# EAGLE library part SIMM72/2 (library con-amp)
AMP connector
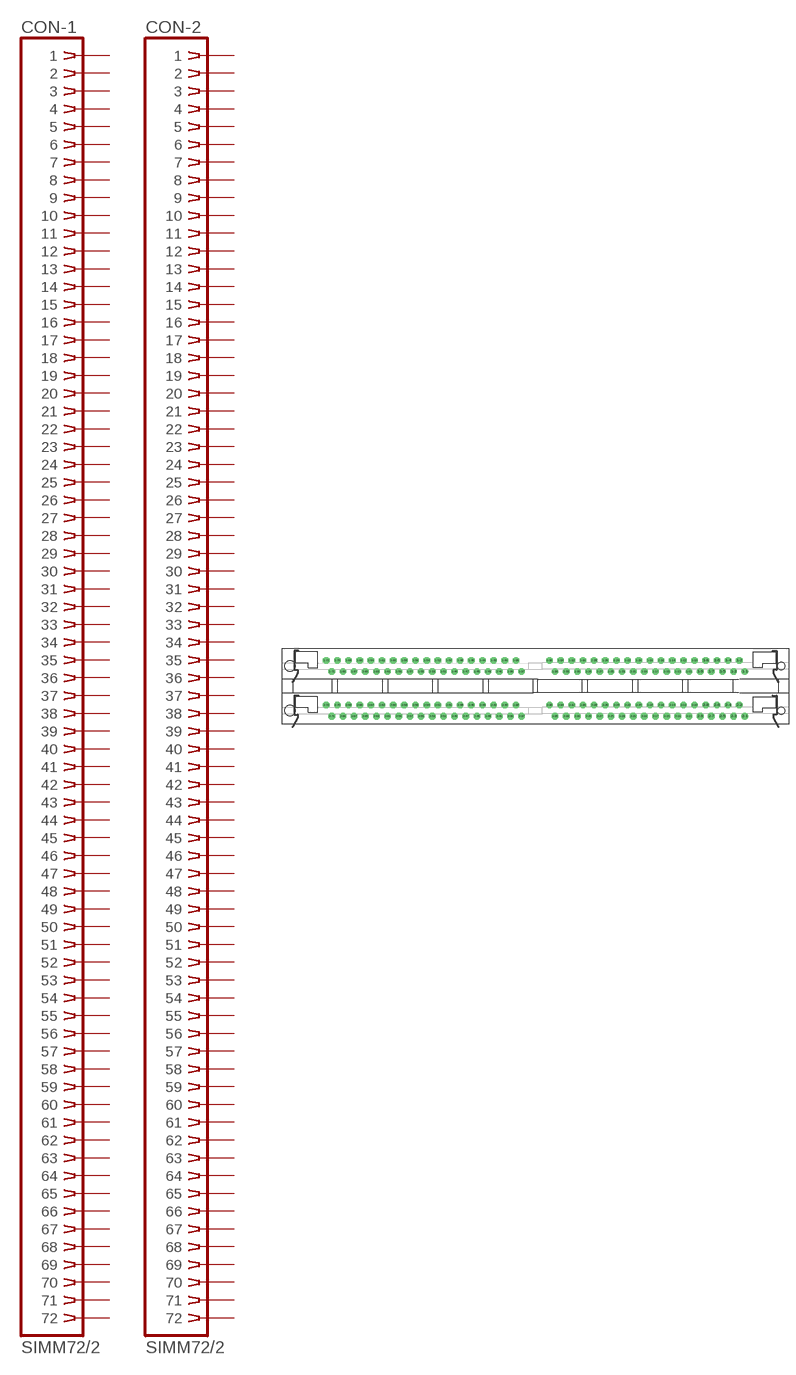
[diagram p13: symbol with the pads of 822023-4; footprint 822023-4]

Designator prefix CON; gates -1=SIMM72 -2=SIMM72

## SIMM72/2 (OC_FARNELL: unknown; OC_NEWARK: unknown)  [822023-4]
1-1  -1:1  pas
1-2  -1:2  pas
1-3  -1:3  pas
1-4  -1:4  pas
1-5  -1:5  pas
1-6  -1:6  pas
1-7  -1:7  pas
1-8  -1:8  pas
1-9  -1:9  pas
1-10  -1:10  pas
1-11  -1:11  pas
1-12  -1:12  pas
1-13  -1:13  pas
1-14  -1:14  pas
1-15  -1:15  pas
1-16  -1:16  pas
1-17  -1:17  pas
1-18  -1:18  pas
1-19  -1:19  pas
1-20  -1:20  pas
1-21  -1:21  pas
1-22  -1:22  pas
1-23  -1:23  pas
1-24  -1:24  pas
1-25  -1:25  pas
1-26  -1:26  pas
1-27  -1:27  pas
1-28  -1:28  pas
1-29  -1:29  pas
1-30  -1:30  pas
1-31  -1:31  pas
1-32  -1:32  pas
1-33  -1:33  pas
1-34  -1:34  pas
1-35  -1:35  pas
1-36  -1:36  pas
1-37  -1:37  pas
1-38  -1:38  pas
1-39  -1:39  pas
1-40  -1:40  pas
1-41  -1:41  pas
1-42  -1:42  pas
1-43  -1:43  pas
1-44  -1:44  pas
1-45  -1:45  pas
1-46  -1:46  pas
1-47  -1:47  pas
1-48  -1:48  pas
1-49  -1:49  pas
1-50  -1:50  pas
1-51  -1:51  pas
1-52  -1:52  pas
1-53  -1:53  pas
1-54  -1:54  pas
1-55  -1:55  pas
1-56  -1:56  pas
1-57  -1:57  pas
1-58  -1:58  pas
1-59  -1:59  pas
1-60  -1:60  pas
1-61  -1:61  pas
1-62  -1:62  pas
1-63  -1:63  pas
1-64  -1:64  pas
1-65  -1:65  pas
1-66  -1:66  pas
1-67  -1:67  pas
1-68  -1:68  pas
1-69  -1:69  pas
1-70  -1:70  pas
1-71  -1:71  pas
1-72  -1:72  pas
2-1  -2:1  pas
2-2  -2:2  pas
2-3  -2:3  pas
2-4  -2:4  pas
2-5  -2:5  pas
2-6  -2:6  pas
2-7  -2:7  pas
2-8  -2:8  pas
2-9  -2:9  pas
2-10  -2:10  pas
2-11  -2:11  pas
2-12  -2:12  pas
2-13  -2:13  pas
2-14  -2:14  pas
2-15  -2:15  pas
2-16  -2:16  pas
2-17  -2:17  pas
2-18  -2:18  pas
2-19  -2:19  pas
2-20  -2:20  pas
2-21  -2:21  pas
2-22  -2:22  pas
2-23  -2:23  pas
2-24  -2:24  pas
2-25  -2:25  pas
2-26  -2:26  pas
2-27  -2:27  pas
2-28  -2:28  pas
2-29  -2:29  pas
2-30  -2:30  pas
2-31  -2:31  pas
2-32  -2:32  pas
2-33  -2:33  pas
2-34  -2:34  pas
2-35  -2:35  pas
2-36  -2:36  pas
2-37  -2:37  pas
2-38  -2:38  pas
2-39  -2:39  pas
2-40  -2:40  pas
2-41  -2:41  pas
2-42  -2:42  pas
2-43  -2:43  pas
2-44  -2:44  pas
2-45  -2:45  pas
2-46  -2:46  pas
2-47  -2:47  pas
2-48  -2:48  pas
2-49  -2:49  pas
2-50  -2:50  pas
2-51  -2:51  pas
2-52  -2:52  pas
2-53  -2:53  pas
2-54  -2:54  pas
2-55  -2:55  pas
2-56  -2:56  pas
2-57  -2:57  pas
2-58  -2:58  pas
2-59  -2:59  pas
2-60  -2:60  pas
2-61  -2:61  pas
2-62  -2:62  pas
2-63  -2:63  pas
2-64  -2:64  pas
2-65  -2:65  pas
2-66  -2:66  pas
2-67  -2:67  pas
2-68  -2:68  pas
2-69  -2:69  pas
2-70  -2:70  pas
2-71  -2:71  pas
2-72  -2:72  pas

## Footprint 822023-4 (pad centres in mm)
SIMM Socket
drill 1.016 round: 1-1 47.625,-1.27; 2-1 47.625,-11.43
drill 1.016 octagon: 1-2 46.355,1.27; 1-3 45.085,-1.27; 1-4 43.815,1.27; 1-5 42.545,-1.27; 1-6 41.275,1.27; 1-7 40.005,-1.27; 1-8 38.735,1.27; 1-9 37.465,-1.27; 1-10 36.195,1.27; 1-11 34.925,-1.27; 1-12 33.655,1.27; 1-13 32.385,-1.27; 1-14 31.115,1.27; 1-15 29.845,-1.27; 1-16 28.575,1.27; 1-17 27.305,-1.27; 1-18 26.035,1.27; 1-19 24.765,-1.27; 1-20 23.495,1.27; 1-21 22.225,-1.27; 1-22 20.955,1.27; 1-23 19.685,-1.27; 1-24 18.415,1.27; 1-25 17.145,-1.27; 1-26 15.875,1.27; 1-27 14.605,-1.27; 1-28 13.335,1.27; 1-29 12.065,-1.27; 1-30 10.795,1.27; 1-31 9.525,-1.27; 1-32 8.255,1.27; 1-33 6.985,-1.27; 1-34 5.715,1.27; 1-35 4.445,-1.27; 1-36 3.175,1.27; 1-37 -3.175,-1.27; 1-38 -4.445,1.27; 1-39 -5.715,-1.27; 1-40 -6.985,1.27; 1-41 -8.255,-1.27; 1-42 -9.525,1.27; 1-43 -10.795,-1.27; 1-44 -12.065,1.27; 1-45 -13.335,-1.27; 1-46 -14.605,1.27; 1-47 -15.875,-1.27; 1-48 -17.145,1.27; 1-49 -18.415,-1.27; 1-50 -19.685,1.27; 1-51 -20.955,-1.27; 1-52 -22.225,1.27; 1-53 -23.495,-1.27; 1-54 -24.765,1.27; 1-55 -26.035,-1.27; 1-56 -27.305,1.27; 1-57 -28.575,-1.27; 1-58 -29.845,1.27; 1-59 -31.115,-1.27; 1-60 -32.385,1.27; 1-61 -33.655,-1.27; 1-62 -34.925,1.27; 1-63 -36.195,-1.27; 1-64 -37.465,1.27; 1-65 -38.735,-1.27; 1-66 -40.005,1.27; 1-67 -41.275,-1.27; 1-68 -42.545,1.27; 1-69 -43.815,-1.27; 1-70 -45.085,1.27; 1-71 -46.355,-1.27; 1-72 -47.625,1.27; 2-2 46.355,-8.89; 2-3 45.085,-11.43; 2-4 43.815,-8.89; 2-5 42.545,-11.43; 2-6 41.275,-8.89; 2-7 40.005,-11.43; 2-8 38.735,-8.89; 2-9 37.465,-11.43; 2-10 36.195,-8.89; 2-11 34.925,-11.43; 2-12 33.655,-8.89; 2-13 32.385,-11.43; 2-14 31.115,-8.89; 2-15 29.845,-11.43; 2-16 28.575,-8.89; 2-17 27.305,-11.43; 2-18 26.035,-8.89; 2-19 24.765,-11.43; 2-20 23.495,-8.89; 2-21 22.225,-11.43; 2-22 20.955,-8.89; 2-23 19.685,-11.43; 2-24 18.415,-8.89; 2-25 17.145,-11.43; 2-26 15.875,-8.89; 2-27 14.605,-11.43; 2-28 13.335,-8.89; 2-29 12.065,-11.43; 2-30 10.795,-8.89; 2-31 9.525,-11.43; 2-32 8.255,-8.89; 2-33 6.985,-11.43; 2-34 5.715,-8.89; 2-35 4.445,-11.43; 2-36 3.175,-8.89; 2-37 -3.175,-11.43; 2-38 -4.445,-8.89; 2-39 -5.715,-11.43; 2-40 -6.985,-8.89; 2-41 -8.255,-11.43; 2-42 -9.525,-8.89; 2-43 -10.795,-11.43; 2-44 -12.065,-8.89; 2-45 -13.335,-11.43; 2-46 -14.605,-8.89; 2-47 -15.875,-11.43; 2-48 -17.145,-8.89; 2-49 -18.415,-11.43; 2-50 -19.685,-8.89; 2-51 -20.955,-11.43; 2-52 -22.225,-8.89; 2-53 -23.495,-11.43; 2-54 -24.765,-8.89; 2-55 -26.035,-11.43; 2-56 -27.305,-8.89; 2-57 -28.575,-11.43; 2-58 -29.845,-8.89; 2-59 -31.115,-11.43; 2-60 -32.385,-8.89; 2-61 -33.655,-11.43; 2-62 -34.925,-8.89; 2-63 -36.195,-11.43; 2-64 -37.465,-8.89; 2-65 -38.735,-11.43; 2-66 -40.005,-8.89; 2-67 -41.275,-11.43; 2-68 -42.545,-8.89; 2-69 -43.815,-11.43; 2-70 -45.085,-8.89; 2-71 -46.355,-11.43; 2-72 -47.625,-8.89
hole 2.438 at -55.88,0
hole 1.626 at 55.88,0
hole 2.438 at -55.88,-10.16
hole 1.626 at 55.88,-10.16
